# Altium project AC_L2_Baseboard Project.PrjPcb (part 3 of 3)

## Sheet AC_L2_Baseboard_HPGP_ZC.SchDoc
size 431 x 279 mm; DocumentNumber: 5; SheetNumber: 5; SheetTotal: 11; PageSetup: Record=PageOptions¦CenterHorizontal=True¦CenterVertical=True¦PrintScale=0.69¦XCorrection=1.00¦YCorrection=1.00¦PrintKind=0¦BorderSize=5000000¦LeftOffset=0¦BottomOffset=0¦Orientation=2¦PaperLength=1000¦PaperWidth=1000¦Scale=100¦PaperSource=15¦PrintQuality=600¦MediaType=1¦DitherType=10¦PaperKind=Letter¦PrintScaleMode=1
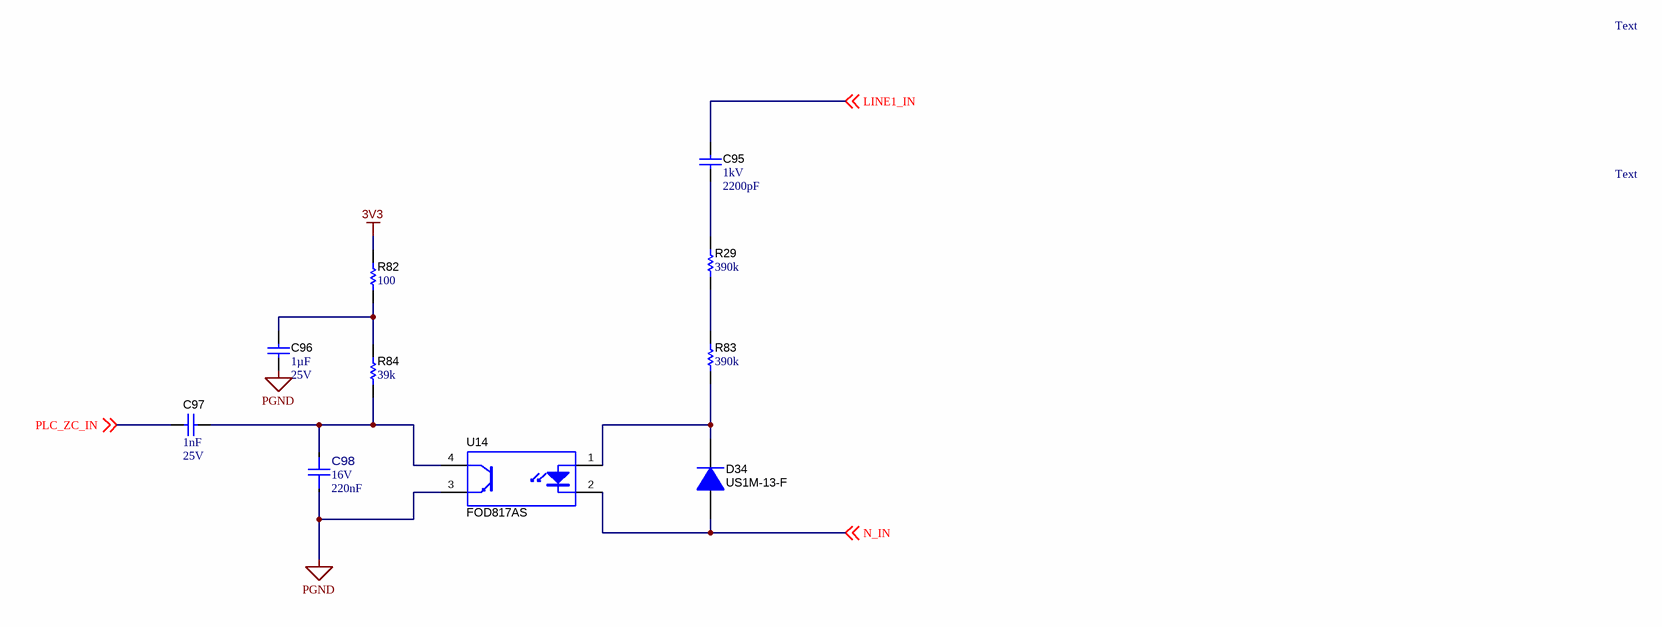
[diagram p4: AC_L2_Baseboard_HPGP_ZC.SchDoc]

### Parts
C95  VDC_V: 1kV  ValueDisplayed: 2200pF  [1206]  (hidden comment: GRM31BR73A222KW01L)
C96  Cap_F: 1µF  VDC_V: 25V  [0603]  (hidden comment: GCM188R71E105KA64D)
C97  Cap_F: 1nF  VDC_V: 25V  [0603]  (hidden comment: GRM188R71E102KA01D)
C98  VDC_V: 16V  Cap_F: 220nF  [FP-CC0603KRX7R7BB224_0603-MFG]  (hidden comment: CC0603KRX7R7BB224)
D34  US1M-13-F  [SMA]
R29  ValueDisplayed: 390k  [1206]  (hidden comment: CRCW1206390KJNEA)
R82  ValueDisplayed: 100  [0603]  (hidden comment: CRCW0603100RJNEA)
R83  ValueDisplayed: 390k  [1206]  (hidden comment: CRCW1206390KJNEA)
R84  ValueDisplayed: 39k  [0603]  (hidden comment: RC0603JR-0739KL)
U14  FOD817AS  [N04C]

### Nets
3V3: R82.2
PGND: C96.2 C98.1 U14.3(E)
LINE1_IN: C95.1 ; off-sheet LINE1_IN
N_IN: D34.2(A) U14.2(K) ; off-sheet N_IN
PLC_ZC_IN: C97.2 ; off-sheet PLC_ZC_IN
NetC95_2: C95.2 R29.2
NetC96_1: C96.1 R82.1 R84.2
NetC97_1: C97.1 C98.2 R84.1 U14.4(C)
NetD34_1: D34.1(K) R83.1 U14.1(A)
NetR29_1: R29.1 R83.2

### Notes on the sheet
- Text

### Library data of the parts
C95 = CMP-0008918-2: CAP, CERM, 2200 pF, 1000 V, +/- 10%, X7R, 1206; Manufacturer: MuRata; TaMin_C: -55°C; Polarized: N; SizeAreaWB_mm2: 10.92; Value1: Unknown; U/M: EA; Value: 2200pF; TaMax_C: 125°C; SizeZ_mm: 1.35; SizeX_mm: 3.2; SizeY_mm: 1.6; Value2: 1000V; SizeArea_mm2: 5.12; Cap_F: 2.2nF; AEC Category: Q200
C96 = CMP-0007139-2: CAP, CERM, 1 uF, 25 V, +/- 10%, X7R, AEC-Q200 Grade 1, 0603; Manufacturer: MuRata; TaMin_C: -55°C; Polarized: N; SizeAreaWB_mm2: 4.68; Value1: Unknown; U/M: EA; Value: 1uF; TaMax_C: 125°C; SizeZ_mm: 1; SizeX_mm: 1.6; SizeY_mm: 0.8; SizeArea_mm2: 1.28; AEC Qualified: Y; AEC Category: Q200
C97 = CMP-0007402-2: CAP, CERM, 1000 pF, 25 V, +/- 10%, X7R, 0603; Manufacturer: MuRata; TaMin_C: -55°C; Polarized: N; SizeAreaWB_mm2: 4.68; Value1: Unknown; U/M: EA; Value: 1000pF; TaMax_C: 125°C; SizeZ_mm: 1; SizeX_mm: 1.6; SizeY_mm: 0.8; SizeArea_mm2: 1.28; AEC Category: Q200
C98 = CMP-0091480-1: 0603 0.22 uF 16 V ±10 % Tolerance X7R SMT Multilayer Ceramic Capacitor; Manufacturer: Yageo; TempCo: 15%; AEC Qualified: No; Tolerance_%: 10%; Value: 220nF; SizeZ_mm: 0.9mm
D34 = CMP-0076882-1: Diode, Ultrafast, 1000 V, 1 A, SMA; Manufacturer: Diodes Inc.; SizeAreaWB_mm2: 37.3428; Vr_V: 1kV; SizeArea_mm2: 16.3228; TJmax_C: 150°C; AEC Category: Q101; Value: 1000V; SizeZ_mm: 2.87; Green_REACh: Incomplete; Io_A: 1A; Vf_V: 1.7V; SizeY_mm: 2.92; Green_Lifecycle: Not Set; U/M: EA; SizeX_mm: 5.59; RJC_CperW: 30.0
R29 R83 = CMP-0018664-3: RES, 390 k, 5%, 0.25 W, AEC-Q200 Grade 0, 1206; Manufacturer: Vishay-Dale; Power_W: 250mW; TempCo: 200 ppm/C; Value: 390k; EIA_Code: E24; SizeX_mm: 3.2; SizeY_mm: 1.6; SizeZ_mm: 1.35; Value2: 0.25W; SizeArea_mm2: 5.12; AEC Qualified: Y; VDC_V: 200V; AEC Category: Q200; AEC Grade: 0
R82 = CMP-0025700-2: RES, 100, 5%, 0.1 W, 0603; Manufacturer: Vishay-Dale; Power_W: 100mW; TempCo: 200 ppm/C; Value_Code: 100R; U/M: EA; Value: 100; EIA_Code: E24; SizeX_mm: 1.6; SizeY_mm: 0.8; SizeZ_mm: 1; Value2: 0.1W; SizeArea_mm2: 1.28; VDC_V: 75V; AEC Category: Q200
R84 = CMP-0025917-5: RES, 39 k, 5%, 0.1 W, 0603; Manufacturer: Yageo; Power_W: 100mW; TempCo: 100 ppm/C; Value_Code: 39k0; Value: 39k; EIA_Code: E24; SizeX_mm: 1.6; SizeY_mm: 0.8; SizeZ_mm: 1; Value2: 0.1W; SizeArea_mm2: 1.28; AEC Qualified: N; VDC_V: 75V; AEC Category: Q200; SizeAreaWB_mm2: 4.68
U14 = CMP-0006177-3: Optocoupler, 5 kV, 80-160% CTR, SMT; Manufacturer: Fairchild Semiconductor; CTR (Max): 160%; CTR (Min): 80%; Voltage_Isolation_Vrms: 5kV

## Sheet AC_L2_Baseboard_Pilot_Wire_ADC.SchDoc
size 431 x 279 mm; DocumentNumber: 6; SheetNumber: 6; SheetTotal: 11; PageSetup: Record=PageOptions¦CenterHorizontal=True¦CenterVertical=True¦PrintScale=0.69¦XCorrection=1.00¦YCorrection=1.00¦PrintKind=0¦BorderSize=5000000¦LeftOffset=0¦BottomOffset=0¦Orientation=2¦PaperLength=1000¦PaperWidth=1000¦Scale=100¦PaperSource=15¦PrintQuality=600¦MediaType=1¦DitherType=10¦PaperKind=Letter¦PrintScaleMode=1
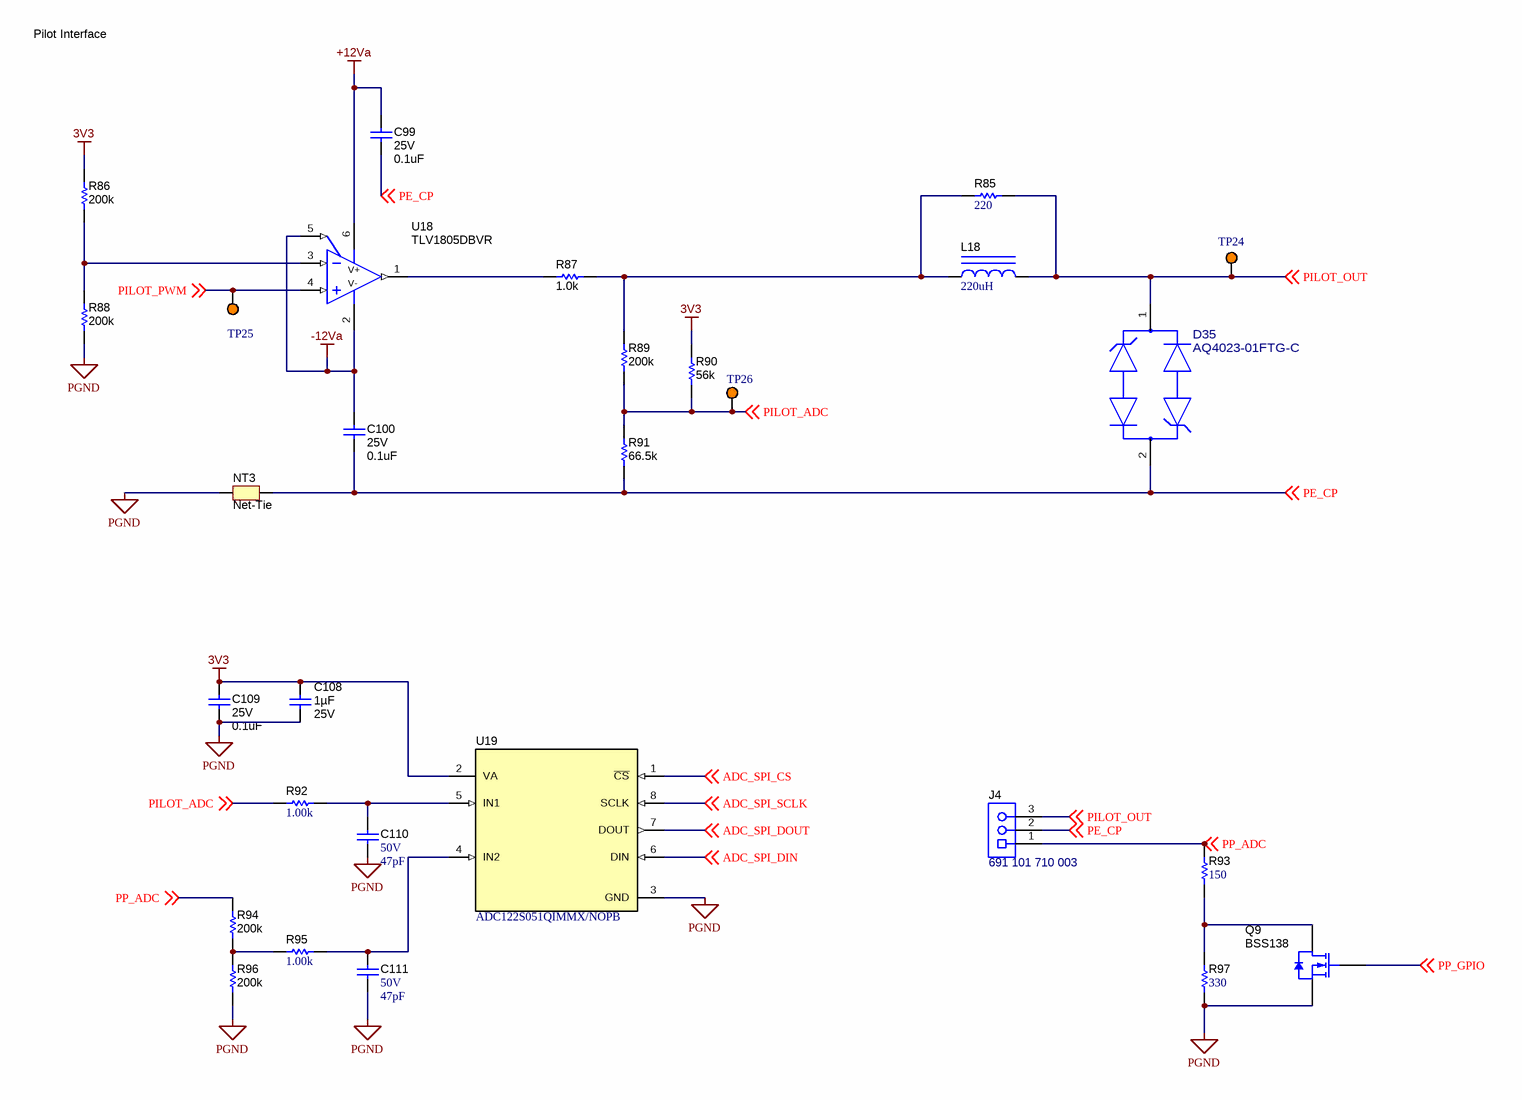
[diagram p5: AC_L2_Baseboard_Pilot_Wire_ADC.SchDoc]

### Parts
C99  VDC_V: 25V  ValueDisplayed: 0.1uF  [0603]  (hidden comment: GRM188R71E104KA01D)
C100  VDC_V: 25V  ValueDisplayed: 0.1uF  [0603]  (hidden comment: GRM188R71E104KA01D)
C108  Cap_F: 1µF  VDC_V: 25V  [0603]  (hidden comment: CGJ3E1X7R1E105K080AC)
C109  VDC_V: 25V  ValueDisplayed: 0.1uF  [0603]  (hidden comment: GRM188R71E104KA01D)
C110  VDC_V: 50V  ValueDisplayed: 47pF  [0603]  (hidden comment: CGA3E2NP01H470J080AA)
C111  VDC_V: 50V  ValueDisplayed: 47pF  [0603]  (hidden comment: CGA3E2NP01H470J080AA)
D35  AQ4023-01FTG-C  [FP-AQ4023-01FTG-C_SOD323-MFG]
J4  691 101 710 003  [Wurth_691101710003]
L18  ValueDisplayed: 220uH  [WE-PD_7345_PlasticBase]  (hidden comment: 7447779222)
NT3  Net-Tie  [Net-Tie_0805_HV_NoOverlay]  (net tie, no BOM)
Q9  BSS138  [SOT-23]
R85  ValueDisplayed: 220  [0603]  (hidden comment: CRCW0603220RJNEA)
R86  ValueDisplayed: 200k  [0603]  (hidden comment: RC0603FR-07200KL)
R87  ValueDisplayed: 1.0k  [0603]  (hidden comment: RC0603JR-071KL)
R88  ValueDisplayed: 200k  [0603]  (hidden comment: RC0603FR-07200KL)
R89  ValueDisplayed: 200k  [0603]  (hidden comment: RC0603FR-07200KL)
R90  ValueDisplayed: 56k  [0603]  (hidden comment: RC0603JR-0756KL)
R91  ValueDisplayed: 66.5k  [0603]  (hidden comment: RC0603FR-0766K5L)
R92  ValueDisplayed: 1.00k  [0603]  (hidden comment: RC0603FR-071KL)
R93  ValueDisplayed: 150  [0805_HV]  (hidden comment: CRCW0805150RFKEA)
R94  ValueDisplayed: 200k  [0603]  (hidden comment: RC0603FR-07200KL)
R95  ValueDisplayed: 1.00k  [0603]  (hidden comment: RC0603FR-071KL)
R96  ValueDisplayed: 200k  [0603]  (hidden comment: RC0603FR-07200KL)
R97  ValueDisplayed: 330  [0805_HV]  (hidden comment: CRCW0805330RFKEAC)
TP24  5003  [Keystone5003]  (value not drawn)
TP25  5003  [Keystone5003]  (value not drawn)
TP26  5003  [Keystone5003]  (value not drawn)
U18  TLV1805DBVR  [DBV0006A_N]
U19  ADC122S051QIMMX/NOPB  [DGK0008A_N]

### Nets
3V3: C108.1 C109.1 R86.2 R90.2 U19.2(VA)
+12Va: C99.1 U18.6(V+)
-12Va: C100.1 U18.2(V-) U18.5(SD)
PGND: C108.2 C109.2 C110.2 C111.2 NT3.1 Q9.2(S) R88.1 R96.1 R97.1 U19.3(GND)
ADC_SPI_CS: U19.1(~{CS}) ; off-sheet ADC_SPI_CS
ADC_SPI_DIN: U19.6(DIN) ; off-sheet ADC_SPI_DIN
ADC_SPI_DOUT: U19.7(DOUT) ; off-sheet ADC_SPI_DOUT
ADC_SPI_SCLK: U19.8(SCLK) ; off-sheet ADC_SPI_SCLK
PE_CP: C99.2 C100.2 D35.2 J4.2 NT3.2 R91.1 ; off-sheet PE_CP
PILOT_ADC: R89.1 R90.1 R91.2 R92.1 TP26.1 ; off-sheet PILOT_ADC
PILOT_OUT: D35.1 J4.3 L18.2 R85.2 TP24.1 ; off-sheet PILOT_OUT
PILOT_PWM: TP25.1 U18.4(IN+) ; off-sheet PILOT_PWM
PP_ADC: J4.1 R93.2 R94.2 ; off-sheet PP_ADC
PP_GPIO: Q9.1(G) ; off-sheet PP_GPIO
NetC110_1: C110.1 R92.2 U19.5(IN1)
NetC111_1: C111.1 R95.2 U19.4(IN2)
NetL18_1: L18.1 R85.1 R87.2 R89.2
NetQ9_3: Q9.3(D) R93.1 R97.2
NetR86_1: R86.1 R88.2 U18.3(IN-)
NetR87_1: R87.1 U18.1(OUT)
NetR94_1: R94.1 R95.1 R96.2

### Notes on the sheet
- Pilot Interface

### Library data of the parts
C99 C100 C109 = CMP-0007404-4: CAP, CERM, 0.1 uF, 25 V, +/- 10%, X7R, 0603; Manufacturer: MuRata; TaMin_C: -55°C; Polarized: N; SizeAreaWB_mm2: 4.68; Value1: Unknown; U/M: EA; Value: 0.1uF; TaMax_C: 125°C; SizeZ_mm: 1; SizeX_mm: 1.6; SizeY_mm: 0.8; SizeArea_mm2: 1.28; Cap_F: 100nF; AEC Category: Q200
C108 = CMP-0083856-1: CAP, CERM, 1 µF, 25 V,+/- 10%, X7R, 0603; Manufacturer: TDK; TaMin_C: -55°C; Polarized: N; SizeAreaWB_mm2: 4.68; U/M: EA; Value: 1uF; TaMax_C: 125°C; SizeZ_mm: 1; SizeX_mm: 1.6; SizeY_mm: 0.8; SizeArea_mm2: 1.28; AEC Category: Q200
C110 C111 = CMP-0080062-1: CAP, CERM, 47 pF, 50 V,+/- 5%, C0G/NP0, AEC-Q200 Grade 0, 0603; Manufacturer: TDK; TaMin_C: -55°C; Polarized: N; SizeAreaWB_mm2: 4.68; U/M: EA; Value: 47pF; TaMax_C: 150°C; SizeZ_mm: 1; SizeX_mm: 1.6; SizeY_mm: 0.8; SizeArea_mm2: 1.28; AEC Qualified: Y; AEC Grade: 0; AEC Category: Q200
D35 = CMP-0095193-1: ESD Suppressor Diode TVS Bi-Dir 15V Automotive 2-Pin SOD-323 T/R; Manufacturer: Littelfuse; AEC Grade: Grade 0; Standoff Height: 0mm; Breakdown Voltage: 16V; Direction: Bidirectional; AEC Qualified: Yes; Number Of Channels: 1; ValueDisplayed: 1.3pF; SizeZ_mm: 1mm; Ipp: 12A; Ppk: 450W; Clamping Voltage: 37.5V
J4 = CMP-0054829-1: Terminal Block, 5 mm, 3x1, Tin, TH; Manufacturer: Wurth Elektronik; CNHeader: FALSE; Green_Lifecycle: Active; Green_REACh: Passed; CT: TRUE
L18 = CMP-0064815-2: Inductor, Shielded Drum Core, Metal Composite, 220 uH, 0.44 A, 0.92 ohm, SMD; Manufacturer: Wurth Elektronik; Isat: 0.54A @ 10% inductance drop; Irms: 0.44A @ 40C rise; Green_Lifecycle: Active; SizeAreaWB_mm2: 86.49; DCR_ohm: 0.92; Green_REACh: Passed; Value: 220uH; Imax_A: 440mA; SizeZ_mm: 4.5; SizeX_mm: 7.3; Value2: 0.44A; SizeArea_mm2: 53.29; Ind_H: 220µH; AEC Category: Q200
NT3 = CMP-0078142-2: Single point connection between nets.
Q9 = CMP-0000755-1: MOSFET, N-CH, 50 V, 0.22 A, SOT-23; Alternate Manufacturer: None; Manufacturer: Fairchild Semiconductor; SizeZ_mm: 1.1; ChType: N; Value2: 1.7 nC; VdsMax_V: 50V; SizeX_mm: 2.5; SizeY_mm: 3; Vgs_V: 20V; Value: 50V; Rdson45_ohm: 6; SizeArea_mm2: 7.5; AEC Category: Q101; IdsMax_A: 220mA; SizeAreaWB_mm2: 14; U/M: EA; QgTyp_nC: 1.7
R85 = CMP-0025756-4: RES, 220, 5%, 0.1 W, AEC-Q200 Grade 0, 0603; Manufacturer: Vishay-Dale; Power_W: 100mW; TempCo: 200 ppm/C; Value_Code: 220R; Value: 220; EIA_Code: E24; SizeX_mm: 1.6; SizeY_mm: 0.8; SizeZ_mm: 1; Value2: 0.1W; SizeArea_mm2: 1.28; AEC Qualified: Y; VDC_V: 75V; AEC Category: Q200; AEC Grade: 0
R86 R88 R89 R94 R96 = CMP-0022901-4: RES, 200 k, 1%, 0.1 W, 0603; Manufacturer: Yageo; Power_W: 100mW; TempCo: 100 ppm/C; Value: 200k; EIA_Code: E96; SizeX_mm: 1.6; SizeY_mm: 0.8; SizeZ_mm: 1; Value2: 0.1W; AEC Qualified: N; VDC_V: 75V; AEC Category: Q200; SizeArea_mm2: 1.28; SizeAreaWB_mm2: 4.68
R87 = CMP-0025899-5: RES, 1.0 k, 5%, 0.1 W, 0603; Manufacturer: Yageo; Power_W: 100mW; TempCo: 100 ppm/C; Value_Code: 1k00; Value: 1.0k; EIA_Code: E24; Res_ohm: 1k; SizeX_mm: 1.6; SizeY_mm: 0.8; SizeZ_mm: 1; Value2: 0.1W; SizeArea_mm2: 1.28; AEC Qualified: N; VDC_V: 75V; AEC Category: Q200; SizeAreaWB_mm2: 4.68
R90 = CMP-0025931-5: RES, 56 k, 5%, 0.1 W, 0603; Manufacturer: Yageo; Power_W: 100mW; TempCo: 100 ppm/C; Value_Code: 56k0; Value: 56k; EIA_Code: E24; SizeX_mm: 1.6; SizeY_mm: 0.8; SizeZ_mm: 1; Value2: 0.1W; SizeArea_mm2: 1.28; AEC Qualified: N; VDC_V: 75V; AEC Category: Q200; SizeAreaWB_mm2: 4.68
R91 = CMP-0023232-5: RES, 66.5 k, 1%, 0.1 W, 0603; Manufacturer: Yageo; Power_W: 100mW; TempCo: 100 ppm/C; Value_Code: 66k5; Value: 66.5k; EIA_Code: E96; SizeZ_mm: 1; Value2: 0.1W; SizeArea_mm2: 1.28; AEC Qualified: N; VDC_V: 75V; AEC Category: Q200; SizeAreaWB_mm2: 4.68; SizeX_mm: 1.6; SizeY_mm: 0.8
R92 R95 = CMP-0022895-5: RES, 1.00 k, 1%, 0.1 W, 0603; Manufacturer: Yageo; Power_W: 100mW; TempCo: 100 ppm/C; Value_Code: 1k00; Value: 1.00k; EIA_Code: E96; Res_ohm: 1k; SizeX_mm: 1.6; SizeY_mm: 0.8; SizeZ_mm: 1; Value2: 0.1W; SizeArea_mm2: 1.28; AEC Qualified: N; VDC_V: 75V; AEC Category: Q200; SizeAreaWB_mm2: 4.68
R93 = CMP-0020904-3: RES, 150, 1%, 0.125 W, AEC-Q200 Grade 0, 0805; Manufacturer: Vishay-Dale; Power_W: 125mW; TempCo: 100 ppm/C; Value_Code: 150R; Value: 150; EIA_Code: E96; SizeX_mm: 2; SizeY_mm: 1.25; SizeZ_mm: 1.45; Value2: 0.125W; SizeArea_mm2: 2.5; AEC Qualified: Y; VDC_V: 150V; AEC Category: Q200; AEC Grade: 0
R97 = CMP-0082535-1: RES, 330, 1%, 0.125 W, 0805; Manufacturer: Vishay-Dale; Power_W: 125mW; TempCo: 100 ppm/C; SizeAreaWB_mm2: 6.75; Value_Code: 330R; Value: 330; SizeX_mm: 2; SizeY_mm: 1.25; SizeZ_mm: 1.45; Value2: 0.125W; SizeArea_mm2: 2.5; AEC Qualified: N; VDC_V: 150V; AEC Category: Q200
TP24-TP26 = CMP-0055140-1: Test Point, Miniature, Orange, TH; Manufacturer: Keystone; CNHeader: FALSE; Green_Lifecycle: Active; Green_REACh: Passed; ContactFinish: Silver; CT: TRUE
U18 = CMP-0080757-2: 40 V, microPower, Push-Pull Comparator with Shutdown, DBV0006A (SOT-23-6); Alternate Manufacturer: Texas Instruments; SizeAreaWB_mm2: 14.82; SizeZ_mm: 1.45; SizeX_mm: 2.8; SizeY_mm: 2.9; SizeArea_mm2: 8.12; CompType: IC; AEC Qualified: N; AEC Category: Q200
U19 = CMP-0077684-1: 2 Channel, 200 ksps to 500 ksps  12-Bit A/D Converter, DGK0008A (VSSOP-8); Alternate PartNumber: ADC122S051QIMM/NOPB; Alternate Manufacturer: Texas Instruments; SizeAreaWB_mm2: 35.955; SizeZ_mm: 1.1; SizeX_mm: 5.05; SizeY_mm: 3.1; SizeArea_mm2: 15.655; CompType: IC; AEC Qualified: Y; AEC Category: Q200

## Sheet AC_L2_Baseboard_PlugLock.SchDoc
size 431 x 279 mm; DocumentNumber: 7; SheetNumber: 7; SheetTotal: 11; PageSetup: Record=PageOptions¦CenterHorizontal=True¦CenterVertical=True¦PrintScale=0.69¦XCorrection=1.00¦YCorrection=1.00¦PrintKind=0¦BorderSize=5000000¦LeftOffset=0¦BottomOffset=0¦Orientation=2¦PaperLength=1000¦PaperWidth=1000¦Scale=100¦PaperSource=15¦PrintQuality=600¦MediaType=1¦DitherType=10¦PaperKind=Letter¦PrintScaleMode=1
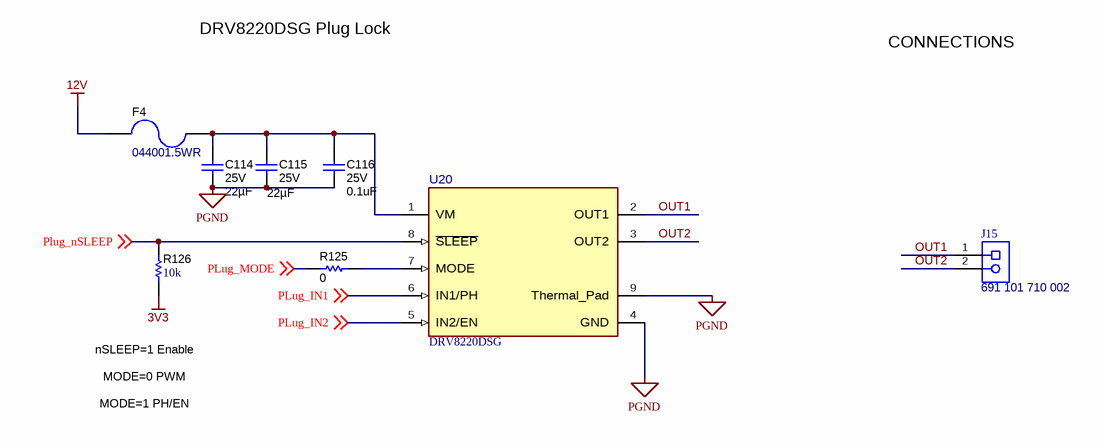
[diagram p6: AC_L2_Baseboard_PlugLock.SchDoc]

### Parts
C114  VDC_V: 25V  ValueDisplayed: 22µF  [1210_270]  (hidden comment: CC1210KKX7R8BB226)
C115  VDC_V: 25V  ValueDisplayed: 22µF  [1210_270]  (hidden comment: CC1210KKX7R8BB226)
C116  VDC_V: 25V  ValueDisplayed: 0.1uF  [0402S]  (hidden comment: TMK105B7104MV-FR)
F4  044001.5WR  [1206]
J15  691 101 710 002  [Wurth_691101710002]
R125  ValueDisplayed: 0  [0603]  (hidden comment: RCS06030000Z0EA)
R126  ValueDisplayed: 10k  [0603]  (hidden comment: RC0603JR-0710KL)
U20  DRV8220DSG  [DSG0008A-MFG]

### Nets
3V3: R126.1
12V: F4.2  [project net 12V_In]
PGND: C114.2 C115.2 C116.2 U20.4(GND) U20.9(Thermal_Pad)
OUT1: J15.1 U20.2(OUT1)
OUT2: J15.2 U20.3(OUT2)
PLug_IN1: U20.6(IN1/PH) ; off-sheet PLug_IN1
PLug_IN2: U20.5(IN2/EN) ; off-sheet PLug_IN2
PLug_MODE: R125.2 ; off-sheet PLug_MODE
Plug_nSLEEP: R126.2 U20.8(~{SLEEP}) ; off-sheet Plug_nSLEEP
NetC114_1: C114.1 C115.1 C116.1 F4.1 U20.1(VM)
NetR125_1: R125.1 U20.7(MODE)

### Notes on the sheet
- DRV8220DSG Plug Lock
- CONNECTIONS
- MODE=0 PWM
- nSLEEP=1 Enable
- MODE=1 PH/EN

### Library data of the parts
C114 C115 = CMP-0082267-1: CAP, CERM, 22 µF, 25 V,+/- 10%, X7R, 1210; Manufacturer: Yageo; TaMin_C: -55°C; ESR_ohm: 1m; Polarized: N; SizeAreaWB_mm2: 14.7; Value1: 0.001 ohm; U/M: EA; Value: 22uF; TaMax_C: 125°C; SizeZ_mm: 2.7; SizeX_mm: 3.2; SizeY_mm: 2.5; Cap_Case: 1210; SizeArea_mm2: 8; AEC Category: Q200
C116 = CMP-0006720-2: CAP, CERM, 0.1 uF, 25 V, +/- 20%, X7R, 0402; Manufacturer: Taiyo Yuden; TaMin_C: -55°C; Polarized: N; SizeAreaWB_mm2: 3; Value1: Unknown; U/M: EA; Value: 0.1uF; TaMax_C: 125°C; SizeZ_mm: 0.6; SizeX_mm: 1; SizeY_mm: 0.5; Cap_Case: 0402; Cap_F: 100nF; AEC Category: Q200
F4 = CMP-0003461-2: Fuse, 1.5 A, 50VAC/VDC, SMD; Manufacturer: Littelfuse; Irating_A: 1.5A; SizeAreaWB_mm2: 10.92; Interrupt_AC: 50A; VAC_V: 50V; SizeZ_mm: 1.35; SizeX_mm: 3.2; SizeY_mm: 1.6; SizeArea_mm2: 5.12; Rtyp_Ohm: 0.1759; MeltingTyp: 0.50652
J15 = CMP-0054828-1: Terminal Block, 5 mm, 2x1, Tin, TH; Manufacturer: Wurth Elektronik; CNHeader: FALSE; Green_Lifecycle: Active; Green_REACh: Passed; CT: TRUE
R125 = CMP-0081973-1: RES, 0, 0%, 0.25 W, AEC-Q200 Grade 0, 0603; Manufacturer: Vishay-Dale; SizeAreaWB_mm2: 4.68; SizeArea_mm2: 1.28; AEC Qualified: Y; AEC Category: Q200; Value: 0; SizeZ_mm: 1; SizeY_mm: 0.8; Power_W: 250mW; Value2: 0.25W; SizeX_mm: 1.6
R126 = CMP-0025886-5: RES, 10 k, 5%, 0.1 W, 0603; Manufacturer: Yageo; Power_W: 100mW; TempCo: 100 ppm/C; Value_Code: 10k0; Value: 10k; EIA_Code: E24; SizeX_mm: 1.6; SizeY_mm: 0.8; SizeZ_mm: 1; Value2: 0.1W; SizeArea_mm2: 1.28; AEC Qualified: N; VDC_V: 75V; AEC Category: Q200; SizeAreaWB_mm2: 4.68
U20 = CMP-0090279-1: 1.6A H-bridge motor driver, PWM, PH/EN, ½ bridge control, with low power sleep mode; Manufacturer: Texas Instruments; Number Of Outputs: 2; Standoff Height: 0mm; TaMin_C: -40°C; Max Supply Voltage: 18V; TJmax_C: +150°C; Motor Type: Brushed; Min Supply Voltage: 4.5V; TaMax_C: +125°C; Switching Frequency: 100kHz; AEC Qualified: No; SizeZ_mm: 0.8mm

## Sheet AC_L2_Baseboard_RCD.SchDoc
size 431 x 279 mm; Date: Not shown in title block; ApprovedBy: Not shown in title block; CheckedBy: Not shown in title block; Author: Not shown in title block; CompanyName: Not shown in title block; Engineer: Not shown in title block; Organization: Not shown in title block; Address1: Not shown in title block; Address2: Not shown in title block; Address3: Not shown in title block; Address4: Not shown in title block; DocumentNumber: 8; Revision: Use project parameter SCH_Rev; SheetNumber: 8; SheetTotal: 11; PageSetup: Record=PageOptions¦CenterHorizontal=True¦CenterVertical=True¦PrintScale=1.00¦XCorrection=1.00¦YCorrection=1.00¦PrintKind=0¦BorderSize=5000000¦LeftOffset=0¦BottomOffset=0¦Orientation=2¦PaperLength=1000¦PaperWidth=1000¦Scale=100¦PaperSource=15¦PrintQuality=600¦MediaType=1¦DitherType=10¦PaperKind=Letter¦PrintScaleMode=1
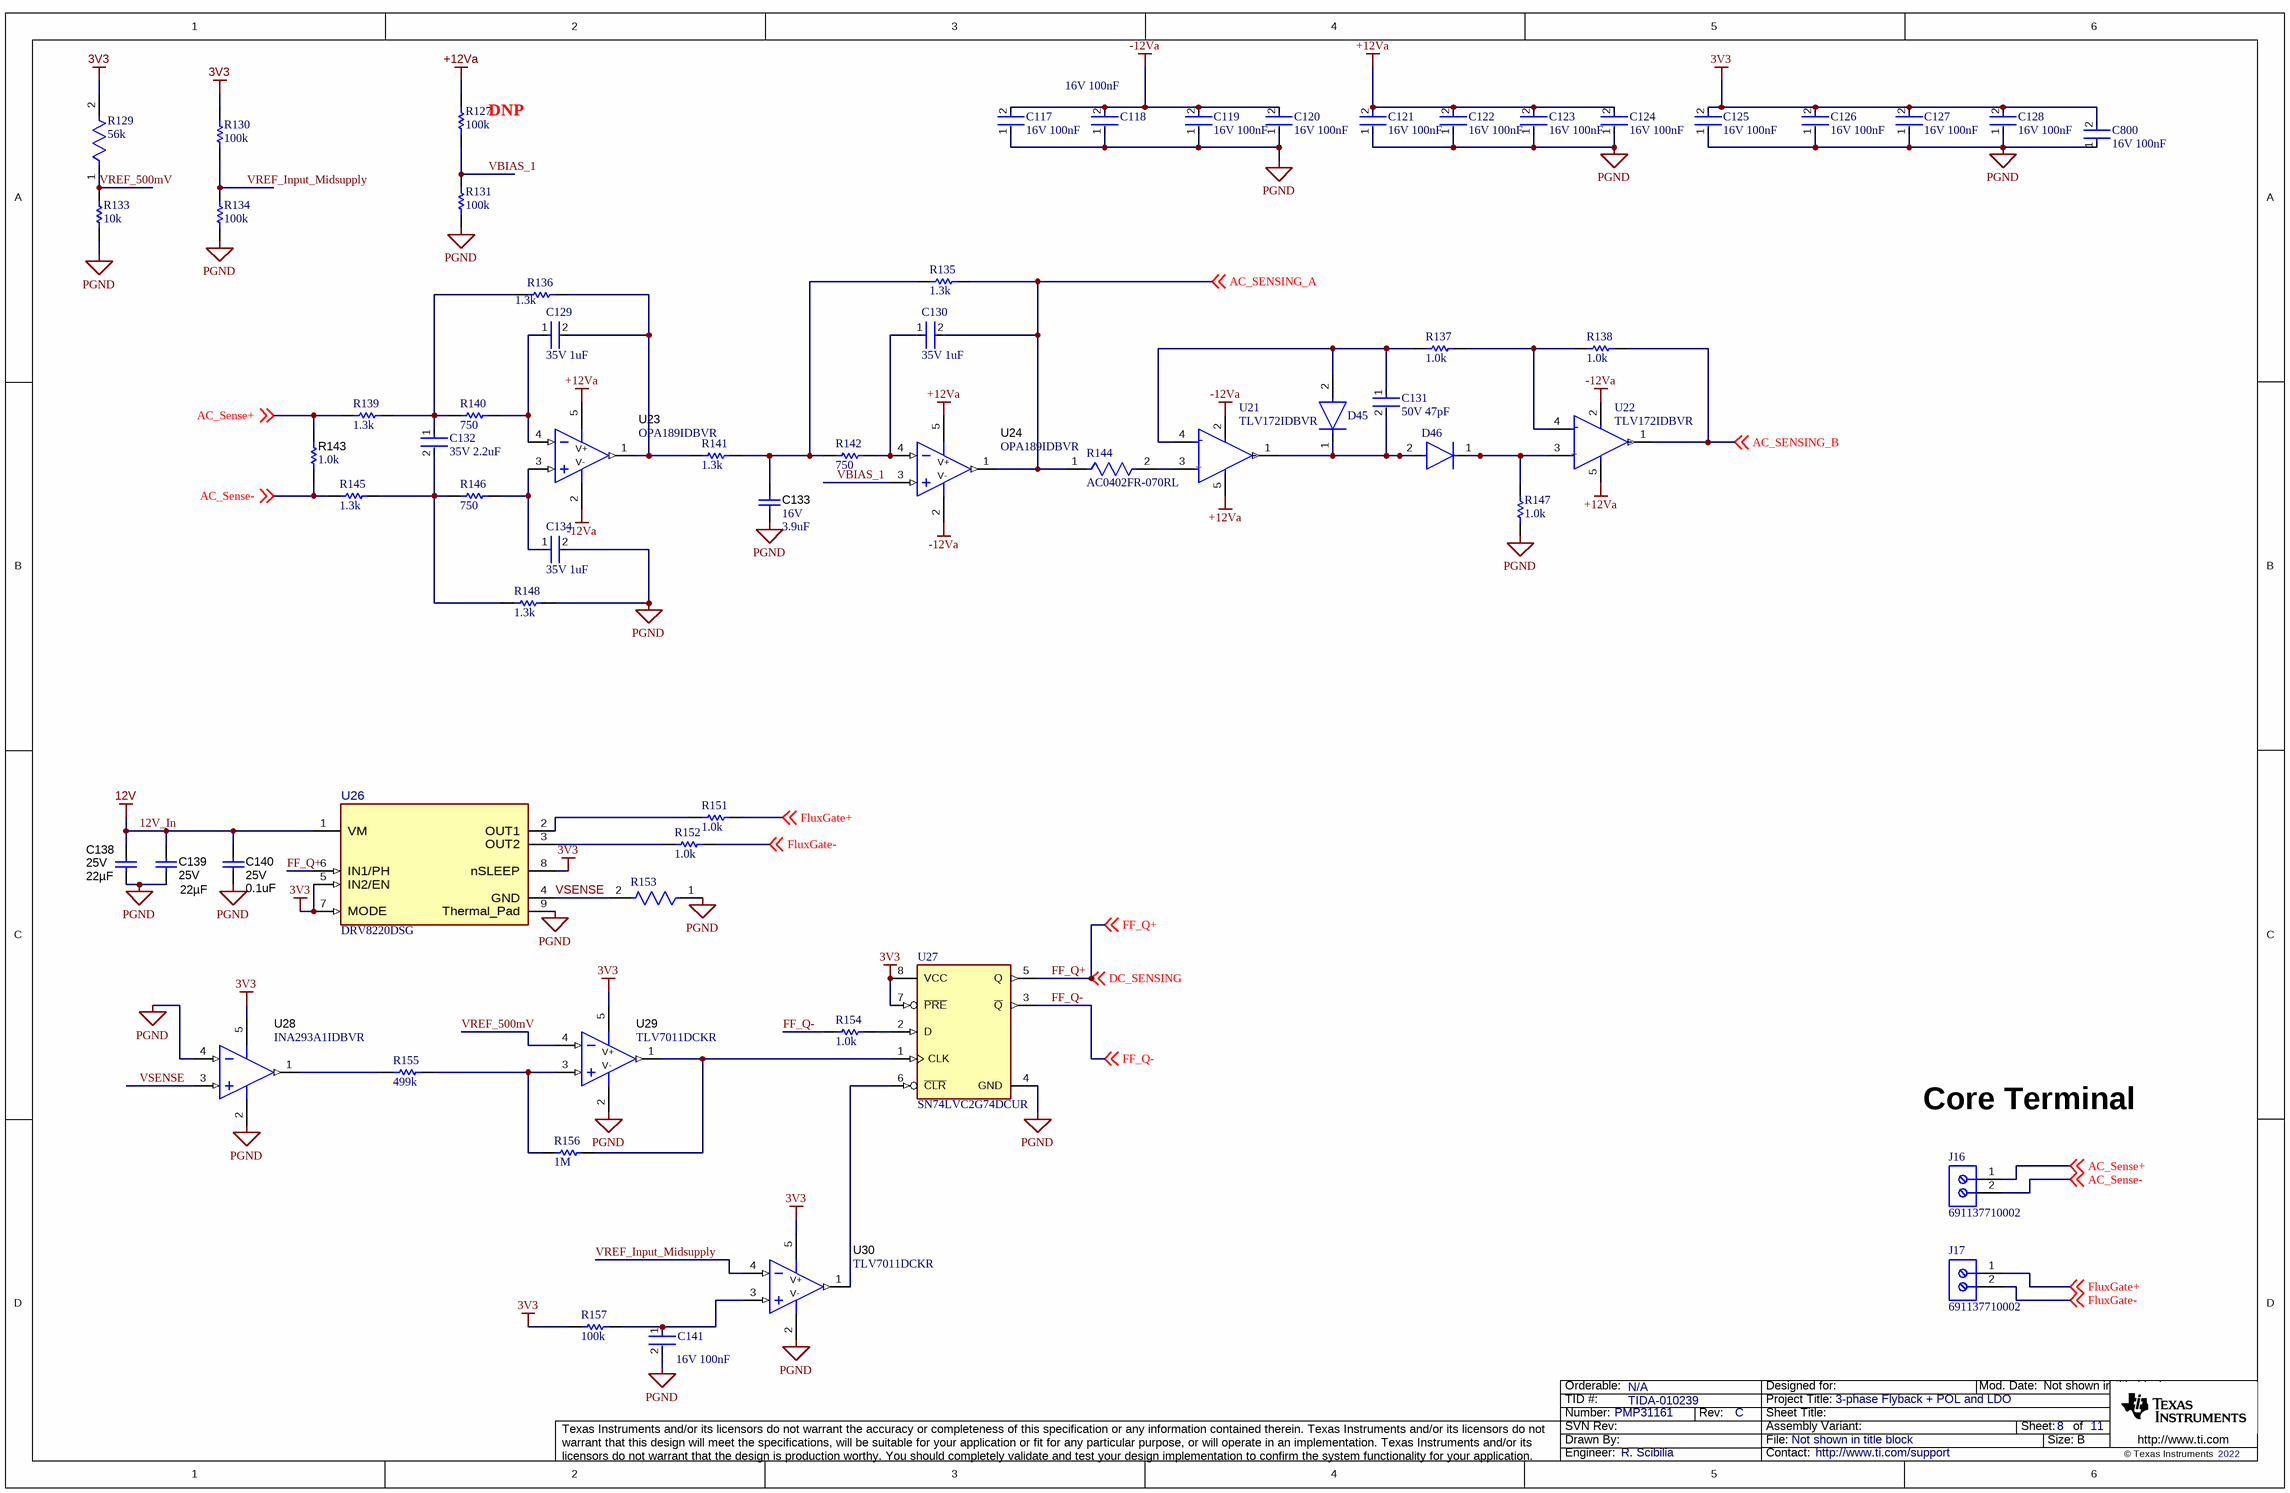
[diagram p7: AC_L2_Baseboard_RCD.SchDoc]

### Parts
C117  16V 100nF  [FP-GRT033-0_03-IPC_B]
C118  16V 100nF  [FP-GRT033-0_03-IPC_B]
C119  16V 100nF  [FP-GRT033-0_03-IPC_B]
C120  16V 100nF  [FP-GRT033-0_03-IPC_B]
C121  16V 100nF  [FP-GRT033-0_03-IPC_B]
C122  16V 100nF  [FP-GRT033-0_03-IPC_B]
C123  16V 100nF  [FP-GRT033-0_03-IPC_B]
C124  16V 100nF  [FP-GRT033-0_03-IPC_B]
C125  16V 100nF  [FP-GRT033-0_03-IPC_B]
C126  16V 100nF  [FP-GRT033-0_03-IPC_B]
C127  16V 100nF  [FP-GRT033-0_03-IPC_B]
C128  16V 100nF  [FP-GRT033-0_03-IPC_B]
C129  35V 1uF  [FP-GRM155-0_1-MFG]
C130  35V 1uF  [FP-GRM155-0_1-MFG]
C131  50V 47pF  [FP-C0603-030-0_03-MFG]
C132  35V 2.2uF  [FP-GRM155-0_2-MFG]
C133  VDC_V: 16V  ValueDisplayed: 3.9uF  [1206L]  (hidden comment: C1206C395K4PACTU)
C134  35V 1uF  [FP-GRM155-0_1-MFG]
C138  VDC_V: 25V  ValueDisplayed: 22µF  [1210_270]  (hidden comment: CC1210KKX7R8BB226)
C139  VDC_V: 25V  ValueDisplayed: 22µF  [1210_270]  (hidden comment: CC1210KKX7R8BB226)
C140  VDC_V: 25V  ValueDisplayed: 0.1uF  [0402S]  (hidden comment: TMK105B7104MV-FR)
C141  16V 100nF  [FP-C0201-AB-MFG]
C800  16V 100nF  [FP-GRT033-0_03-IPC_B]
D45  1N914BWT  [FP-502-01-MFG]  (value not drawn)
D46  1N914BWT  [FP-502-01-MFG]  (value not drawn)
J16  691137710002  [691137710002]
J17  691137710002  [691137710002]
R127  100k  [RESC0603X28X15LL05T05]
R129  56k  [FP-RG1005-IPC_B]
R130  100k  [RESC0603X28X15LL05T05]
R131  100k  [RESC0603X28X15LL05T05]
R133  10k  [RESC0603X28X15LL05T05]
R134  100k  [RESC0603X28X15LL05T05]
R135  1.3k  [RESC0603X28X15LL05T05]
R136  1.3k  [RESC0603X28X15LL05T05]
R137  1.0k  [RESC0603X28X15NL05T05]
R138  1.0k  [RESC0603X28X15NL05T05]
R139  1.3k  [RESC0603X28X15LL05T05]
R140  750  [RESC0603X28X15LL05T05]
R141  1.3k  [RESC0603X28X15LL05T05]
R142  750  [RESC0603X28X15LL05T05]
R143  ValueDisplayed: 1.0k  [2512]  (hidden comment: ERJ-1TYJ102U)
R144  AC0402FR-070RL  [FP-AC0402-0_37-IPC_B]
R145  1.3k  [RESC0603X28X15LL05T05]
R146  750  [RESC0603X28X15LL05T05]
R147  1.0k  [RESC0603X28X15NL05T05]
R148  1.3k  [RESC0603X28X15LL05T05]
R151  1.0k  [RESC0603X28X15NL05T05]
R152  1.0k  [RESC0603X28X15NL05T05]
R153  CRCW12063R00JNEA  [FP-CRCW1206-e3-IPC_A]  (value not drawn)
R154  1.0k  [RESC0603X28X15NL05T05]
R155  499k  [RESC0603X28X15NL05T05]
R156  1M  [RESC0603X28X15LL05T05]
R157  100k  [RESC0603X28X15LL05T05]
U21  TLV172IDBVR  [FP-DBV0005A-IPC_C]
U22  TLV172IDBVR  [FP-DBV0005A-IPC_C]
U23  OPA189IDBVR  [DBV0005A_N]
U24  OPA189IDBVR  [DBV0005A_N]
U26  DRV8220DSG  [DSG0008A-MFG]
U27  SN74LVC2G74DCUR  [FP-DCU0008A-IPC_C]
U28  INA293A1IDBVR  [DBV0005A_M]
U29  TLV7011DCKR  [DCK0005A_N]
U30  TLV7011DCKR  [DCK0005A_N]

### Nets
3V3: C125.2 C126.2 C127.2 C128.2 C800.2 R129.2 R130.2 R157.1 U26.5(IN2/EN) U26.7(MODE) U26.8(nSLEEP) U27.7(~{PRE}) U27.8(VCC) U28.5(V+) U29.5(V+) U30.5(V+)
12V_In: C138.1 C139.1 C140.1 U26.1(VM)  [also labelled 12V]
+12Va: C121.2 C122.2 C123.2 C124.2 R127.2 U21.5(V+) U22.5(V+) U23.5(V+) U24.5(V+)
-12Va: C117.2 C118.2 C119.2 C120.2 U21.2(V-) U22.2(V-) U23.2(V-) U24.2(V-)
PGND: C117.1 C118.1 C119.1 C120.1 C121.1 C122.1 C123.1 C124.1 C125.1 C126.1 C127.1 C128.1 C133.2 C134.2 C138.2 C139.2 C140.2 C141.2 C800.1 R131.1 R133.1 R134.1 R147.1 R148.2 R153.1 U26.9(Thermal_Pad) U27.4(GND) U28.2(GND) U28.4(VIN-) U29.2(V-) U30.2(V-)
AC_Sense+: J16.1 R139.1 R143.2 ; off-sheet AC_Sense+
AC_Sense-: J16.2 R143.1 R145.1 ; off-sheet AC_Sense-
AC_SENSING_A: C130.2 R135.2 R144.1 U24.1(OUT) ; off-sheet AC_SENSING_A
AC_SENSING_B: R138.2 U22.1(OUT) ; off-sheet AC_SENSING_B
FF_Q+: U26.6(IN1/PH) U27.5(Q) ; off-sheet DC_SENSING, off-sheet FF_Q+  [also labelled DC_SENSING]
FF_Q-: R154.1 U27.3(~{Q}) ; off-sheet FF_Q-
FluxGate+: J17.1 R151.2 ; off-sheet FluxGate+
FluxGate-: J17.2 R152.2 ; off-sheet FluxGate-
VBIAS_1: R127.1 R131.2 U24.3(IN+)
VREF_500mV: R129.1 R133.2 U29.4(IN-)
VREF_Input_Midsupply: R130.1 R134.2 U30.4(IN-)
VSENSE: R153.2 U26.4(GND) U28.3(VIN+)
NetC129_1: C129.1 R140.2 U23.4(IN-)
NetC129_2: C129.2 R136.2 R141.1 U23.1(OUT)
NetC130_1: C130.1 R142.2 U24.4(IN-)
NetC131_1: C131.1 D45.2(A) R137.1 U21.4(-IN)
NetC131_2: C131.2 D45.1(C) D46.2(A) U21.1(OUT)
NetC132_1: C132.1 R136.1 R139.2 R140.1
NetC132_2: C132.2 R145.2 R146.1 R148.1
NetC133_1: C133.1 R135.1 R141.2 R142.1
NetC134_1: C134.1 R146.2 U23.3(IN+)
NetC141_1: C141.1 R157.2 U30.3(IN+)
NetD46_1: D46.1(C) R147.2 U22.3(+IN)
NetR137_2: R137.2 R138.1 U22.4(-IN)
NetR144_2: R144.2 U21.3(+IN)
NetR151_1: R151.1 U26.2(OUT1)
NetR152_1: R152.1 U26.3(OUT2)
NetR154_2: R154.2 U27.2(D)
NetR155_1: R155.1 U28.1(OUT)
NetR155_2: R155.2 R156.1 U29.3(IN+)
NetR156_2: R156.2 U27.1(CLK) U29.1(OUT)
NetU27_6: U27.6(~{CLR}) U30.1(OUT)

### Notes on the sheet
- (near R127) DNP
- Core Terminal

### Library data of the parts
C117-C128 C800 = CMP-06035-045930-1: Multi-Layer Ceramic Capacitor 100nF 16V X5R ±10% 0201 Paper T/R GRT033R61C104KE01D
C129 C130 C134 = CMP-06035-015284-1: Chip Multilayer Ceramic Capacitors for General Purpose, 0402, 1.0uF, X5R, 15%, 20%, 35V GRM155R6YA105ME11D
C131 = CMP-08246-004934-1: Multilayer Ceramic Capacitors 47pF ±10% 50V C0G SMD 0201 C0603C0G1H470K030BA
C132 = CMP-06035-031599-1: Chip Multilayer Ceramic Capacitors for General Purpose, 0402, 2.2uF, X5R, 15%, 10%, 35V GRM155R6YA225KE11D
C133 = CMP-0008620-2: CAP, CERM, 3.9 uF, 16 V, +/- 10%, X5R, 1206; Manufacturer: Kemet; TaMin_C: -55°C; ESR_ohm: 0.012; Polarized: N; SizeAreaWB_mm2: 10.92; Value1: 0.012 ohm; U/M: EA; Value: 3.9uF; TaMax_C: 85°C; SizeZ_mm: 1.35; SizeX_mm: 3.2; SizeY_mm: 1.6; Cap_Case: 1206; SizeArea_mm2: 5.12; Cap_F: 3.9µF; IRMS_A: 5.05A; AEC Category: Q200
C138 C139 = CMP-0082267-1: as C114 on sheet AC_L2_Baseboard_PlugLock
C140 = CMP-0006720-2: as C116 on sheet AC_L2_Baseboard_PlugLock
C141 = CMP-1033-00642-2: CAP CER 10000PF 16V 10% X5R 0201 C0201C103K4PACTU; Manufacturer: KEMET; Tolerance: 0.1; Material: Ceramic; Value: 10,000 pF; Standoff Height: 0mm; Temperature Coefficient: 30ppm/°C
D45 D46 = CMP-07163-000008-1: DIODE GEN PURP 75V 200MA SOD523F; Manufacturer: ON Semiconductor; Forward Current: 300mA; Capacitance: 4pF; Max Junction Temp: +150°C; Reverse Voltage: 100V; Value: 4pF; Peak Reverse Current: 5uA
J16 J17 = CMP-1502-03324-1: Series 1377 - 5.00 mm Horizontal Entry with Pressure Clamp WR-TBL, 2 pin; Manufacturer: Wurth Elektronik; Pin Number: 2; Pitch: 5.00mm
R127 R130 R131 R134 R157 = CMP-2004-00003-1: CRCW0201100KFNED; Manufacturer: Vishay
R129 = CMP-2002-01478-2: Automotive Metal Thin Film Chip Resistor, 0402, 56kΩ, 0.1%, 25ppm/°C, 0.0625W, 75V; Voltage Rating: 25V; Power Rating: 30mW; Resistance: 56kR; Max Power Dissipation: 63mW
R133 = CMP-2004-00015-1: CRCW020110K0FKED; Manufacturer: Vishay Dale
R135 R139 R141 R145 R148 = CMP-2004-03995-1: Part Number: CPF0201D3K83E1; Manufacturer: TE Connectivity / AMP
R136 = CMP-2004-00232-1: CRCW02011K30FNED; Manufacturer: Vishay Dale
R137 R138 R147 R151 R152 R154 = CMP-2004-00208-1: CRCW02011K00FKED; Manufacturer: Vishay Dale
R140 R142 R146 = CMP-2004-00846-1: CRCW0201750RFKED; Manufacturer: Vishay Dale
R143 = CMP-0016024-1: RES, 1.0 k, 5%, 1 W, 2512; Manufacturer: Panasonic; Power_W: 1W; TempCo: 200 ppm/C; Value_Code: 1k00; U/M: EA; Value: 1.0k; EIA_Code: E24; Res_ohm: 1k; SizeX_mm: 6.3; SizeY_mm: 3.2; SizeZ_mm: 0.71; SizeArea_mm2: 20.16; VDC_V: 200V; AEC Category: Q200
R144 = CMP-2002-01772-2: RESISTOR 0402 JUMPER ZERO OHM; Voltage Rating: 50V; Temperature Coefficient: 200ppm/°C; Tolerance: 1%; Power Rating: 62.5mW; Resistance: 0R
R153 = CMP-1014-00013-3: RES Thick Film, 3Ω, 5%, 0.25W, 200ppm/°C, 1206; Voltage Rating (DC): 200V; Resistance: 3R; Power Rating: 250mW
R155 = CMP-2004-00650-1: CRCW0201499KFNED; Manufacturer: Vishay Dale
R156 = CMP-2004-00269-1: CRCW02011M00FKED; Manufacturer: Vishay Dale
U21 U22 = CMP-04895-000139-1: IC OPAMP GP 1 CIRCUIT SOT23-5; Input Bias Current: 10pA; Slew Rate: 10V/µs; Gain Bandwidth Product: 10MHz; Input Offset Voltage (Vos): 500uV; Output Current per Channel: 75mA; Operating Supply Current: 1.6mA; Number of Channels: 1
U23 U24 = CMP-0860961-1: 14MHz, MUX-friendly, low-noise, zero-drift, RRO, CMOS precision operational amplifier, DBV0005A (SOT-23-5); Alternate Manufacturer: Texas Instruments; Alternate PartNumber: OPA189IDBVT; SizeY_mm: 2.9; AEC Qualified: N; SizeX_mm: 2.8; SizeAreaWB_mm2: 14.82; CompType: IC; SizeZ_mm: 1.45; Rating: Catalog; AEC Category: Q200; SizeArea_mm2: 8.12
U26 = CMP-0089585-1: Low-Voltage H-Bridge Driver; Manufacturer: Texas Instruments; TaMin_C: -40°C; Nominal Supply Current: 600-3000uA; Max Supply Voltage: 18V; TJmax_C: +150°C; Number Of Outputs: 2; Switching Frequency: 100kHz; Min Supply Voltage: 4.5V; AEC Qualified: No; SizeZ_mm: 0.8mm; Motor Type: Brushed; Standoff Height: 0mm; TaMax_C: +85°C
U27 = CMP-0859-00648-4: IC FF D-TYPE SNGL 1BIT US8; Manufacturer: Texas Instruments; Frequency: 140MHz; Standoff Height: 0mm; Propagation Delay: 6.1ns; Logic Function Desc: D Type; Number Of Outputs: 2; Nominal Supply Current: 10uA; Max Supply Voltage: 5.5V; Number Of Inputs: 1; Min Supply Voltage: 1.65V
U28 = CMP-0750213-2: INA293 High-Voltage, High Bandwidth, Unidirectional, 110-V Common-Mode, Current-Sense Amplifier, DBV0005A (SOT-23-5); Alternate Manufacturer: Texas Instruments; Alternate PartNumber: INA293A1IDBVT; SizeZ_mm: 1.45; AEC Qualified: N; CompType: IC; SizeAreaWB_mm2: 14.82; SizeArea_mm2: 8.12; SizeY_mm: 2.9; AEC Category: Q200; SizeX_mm: 2.8
U29 U30 = CMP-0860894-1: Low power, small size comparator with push-pull output, DCK0005A (SOT-SC70-5); Alternate Manufacturer: Texas Instruments; Alternate PartNumber: TLV7011DCKT; CompType: IC; SizeZ_mm: 1.1; SizeY_mm: 2; AEC Qualified: N; AEC Category: Q200; SizeX_mm: 2.1; SizeAreaWB_mm2: 9.3; SizeArea_mm2: 4.2; Rating: Catalog

## Sheet AC_L2_Baseboard_RCD_MCU.SchDoc
size 431 x 279 mm; Date: Not shown in title block; ApprovedBy: Not shown in title block; CheckedBy: Not shown in title block; Author: Not shown in title block; CompanyName: Not shown in title block; Engineer: Not shown in title block; Organization: Not shown in title block; Address1: Not shown in title block; Address2: Not shown in title block; Address3: Not shown in title block; Address4: Not shown in title block; DocumentNumber: 9; Revision: Use project parameter SCH_Rev; SheetNumber: 9; SheetTotal: 11; PageSetup: Record=PageOptions¦CenterHorizontal=True¦CenterVertical=True¦PrintScale=1.00¦XCorrection=1.00¦YCorrection=1.00¦PrintKind=0¦BorderSize=5000000¦LeftOffset=0¦BottomOffset=0¦Orientation=2¦PaperLength=1000¦PaperWidth=1000¦Scale=100¦PaperSource=15¦PrintQuality=600¦MediaType=1¦DitherType=10¦PaperKind=Letter¦PrintScaleMode=1
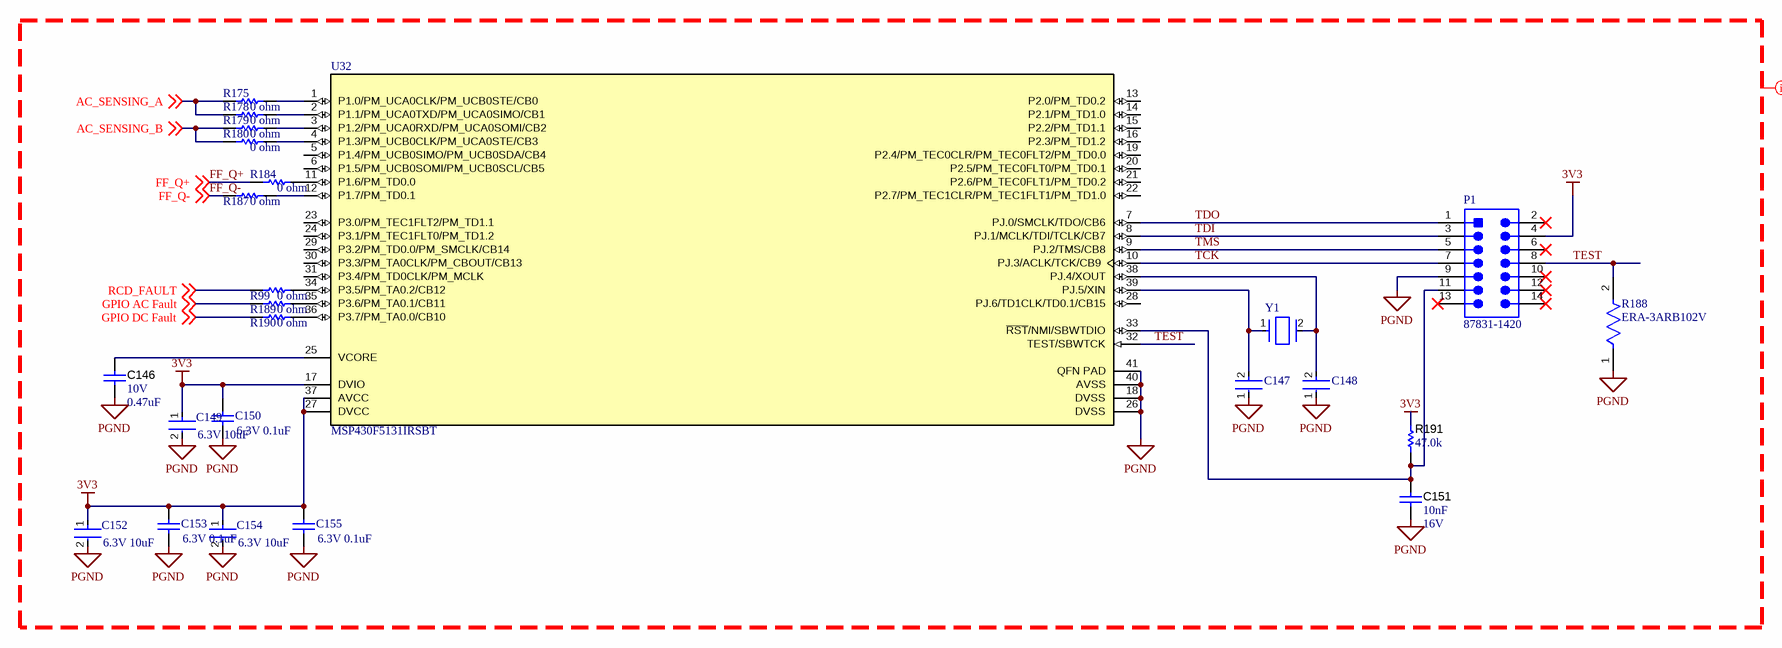
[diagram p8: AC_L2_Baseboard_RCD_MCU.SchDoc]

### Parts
C146  VDC_V: 10V  ValueDisplayed: 0.47uF  [0402]  (hidden comment: GRM155R61A474KE15D)
C147  C1608NP01H060D080AA  [FP-C1608-080-0_1-IPC_B]  (value not drawn)
C148  C1608NP01H060D080AA  [FP-C1608-080-0_1-IPC_B]  (value not drawn)
C149  6.3V 10uF  [FP-GRM155-0_2-MFG]
C150  6.3V 0.1uF  [CAPC1005X56X25NL10T15]
C151  Cap_F: 10nF  VDC_V: 16V  [0603]  (hidden comment: C0603C103K4RACTU)
C152  6.3V 10uF  [FP-GRM155-0_2-MFG]
C153  6.3V 0.1uF  [CAPC1005X56X25NL10T15]
C154  6.3V 10uF  [FP-GRM155-0_2-MFG]
C155  6.3V 0.1uF  [CAPC1005X56X25NL10T15]
P1  87831-1420  [MOLEX-87831-1420_V]
R99  0 ohm  [RESC1005X40X25NL05T10]
R175  0 ohm  [RESC1005X40X25NL05T10]
R178  0 ohm  [RESC1005X40X25NL05T10]
R179  0 ohm  [RESC1005X40X25NL05T10]
R180  0 ohm  [RESC1005X40X25NL05T10]
R184  0 ohm  [RESC1005X40X25NL05T10]
R187  0 ohm  [RESC1005X40X25NL05T10]
R188  ERA-3ARB102V  [FP-ERA3A-IPC_B]
R189  0 ohm  [RESC1005X40X25NL05T10]
R190  0 ohm  [RESC1005X40X25NL05T10]
R191  ValueDisplayed: 47.0k  [0603]  (hidden comment: RC0603FR-0747KL)
U32  MSP430F5131IRSBT  [RSB0040B]
Y1  ABS10-32.768KHZ-1-T  [FP-ABS10-MFG]  (value not drawn)

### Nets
3V3: C149.1 C150.2 C152.1 C153.2 C154.1 C155.2 P1.4 R191.2 U32.17(DVIO) U32.27(DVCC) U32.37(AVCC)
PGND: C146.2 C147.1 C148.1 C149.2 C150.1 C151.2 C152.2 C153.1 C154.2 C155.1 P1.9 R188.1 U32.18(DVSS) U32.26(DVSS) U32.40(AVSS) U32.41(QFN_PAD)
AC_SENSING_A: R175.1 R178.1 ; off-sheet AC_SENSING_A
AC_SENSING_B: R179.1 R180.1 ; off-sheet AC_SENSING_B
FF_Q+: R184.1 ; off-sheet FF_Q+
FF_Q-: R187.1 ; off-sheet FF_Q-
GPIO AC Fault: R189.1 ; off-sheet GPIO AC Fault
GPIO DC Fault: R190.1 ; off-sheet GPIO DC Fault
RCD_FAULT: R99.1 ; off-sheet RCD_FAULT
TCK: P1.7 U32.10(PJ.3/ACLK/TCK/CB9)
TDI: P1.3 U32.8(PJ.1/MCLK/TDI/TCLK/CB7)
TDO: P1.1 U32.7(PJ.0/SMCLK/TDO/CB6)
TEST: P1.8 R188.2 U32.32(TEST/SBWTCK)
TMS: P1.5 U32.9(PJ.2/TMS/CB8)
NetC146_1: C146.1 U32.25(VCORE)
NetC147_2: C147.2 U32.39(PJ.5/XIN) Y1.1
NetC148_2: C148.2 U32.38(PJ.4/XOUT) Y1.2
NetC151_1: C151.1 P1.11 R191.1 U32.33(~{RST}/NMI/SBWTDIO)
NetR99_2: R99.2 U32.34(P3.5/PM_TA0.2/CB12)
NetR175_2: R175.2 U32.1(P1.0/PM_UCA0CLK/PM_UCB0STE/CB0)
NetR178_2: R178.2 U32.2(P1.1/PM_UCA0TXD/PM_UCA0SIMO/CB1)
NetR179_2: R179.2 U32.3(P1.2/PM_UCA0RXD/PM_UCA0SOMI/CB2)
NetR180_2: R180.2 U32.4(P1.3/PM_UCB0CLK/PM_UCA0STE/CB3)
NetR184_2: R184.2 U32.11(P1.6/PM_TD0.0)
NetR187_2: R187.2 U32.12(P1.7/PM_TD0.1)
NetR189_2: R189.2 U32.35(P3.6/PM_TA0.1/CB11)
NetR190_2: R190.2 U32.36(P3.7/PM_TA0.0/CB10)

Not connected (* = marked no-connect by the designer): P1 2* 6* 10* 12* 13* 14*; U32 5(P1.4/PM_UCB0SIMO/PM_UCB0SDA/CB4) 6(P1.5/PM_UCB0SOMI/PM_UCB0SCL/CB5) 13(P2.0/PM_TD0.2) 14(P2.1/PM_TD1.0) 15(P2.2/PM_TD1.1) 16(P2.3/PM_TD1.2) 19(P2.4/PM_TEC0CLR/PM_TEC0FLT2/PM_TD0.0) 20(P2.5/PM_TEC0FLT0/PM_TD0.1) 21(P2.6/PM_TEC0FLT1/PM_TD0.2) 22(P2.7/PM_TEC1CLR/PM_TEC1FLT1/PM_TD1.0) 23(P3.0/PM_TEC1FLT2/PM_TD1.1) 24(P3.1/PM_TEC1FLT0/PM_TD1.2) 28(PJ.6/TD1CLK/TD0.1/CB15) 29(P3.2/PM_TD0.0/PM_SMCLK/CB14) 30(P3.3/PM_TA0CLK/PM_CBOUT/CB13) 31(P3.4/PM_TD0CLK/PM_MCLK)

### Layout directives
mark named MSP430: 3V3, AC_SENSING_A, AC_SENSING_B, FF_Q+, FF_Q-, GPIO AC Fault, GPIO DC Fault, PGND, RCD_FAULT, TCK, TDI, TDO, TEST, TMS

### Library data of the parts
C146 = CMP-0006580-2: CAP, CERM, 0.47 uF, 10 V, +/- 10%, X5R, 0402; Manufacturer: MuRata; TaMin_C: -55°C; Polarized: N; SizeAreaWB_mm2: 3; Value1: Unknown; U/M: EA; Value: 0.47uF; TaMax_C: 85°C; SizeZ_mm: 0.6; SizeX_mm: 1; SizeY_mm: 0.5; Cap_F: 470nF; AEC Category: Q200
C147 C148 = CMP-08246-004279-1: Multilayer Ceramic Capacitors 6pF ±0.5pF 50V NP0 SMD 0603; Dielectric: C0G
C149 C152 C154 = CMP-06035-061139-1: Chip Multilayer Ceramic Capacitors for General Purpose, 0402, 10uF, X5R, 15%, 20%, 6.3V
C150 C153 C155 = CMP-2008-02981-1: 04026C104MAT2A; Manufacturer: AVX Interconnect / Elco
C151 = CMP-0006853-4: CAP, CERM, 0.01 uF, 16 V, +/- 10%, X7R, 0603; Manufacturer: Kemet; TaMin_C: -55°C; Polarized: N; SizeAreaWB_mm2: 4.68; Value1: Unknown; U/M: EA; Value: 0.01uF; TaMax_C: 125°C; SizeZ_mm: 1; SizeX_mm: 1.6; SizeY_mm: 0.8; SizeArea_mm2: 1.28; AEC Category: Q200
P1 = CMP-2000-05240-1: Header, Pitch 2 mm, 2 x 7 Position, Height 6.4 mm, Tail Length 2.5 mm, -55 to 105 degC, RoHS, Tube; Number of Positions / Contacts: 14; Current Rating: 2A; Brand: Molex; Mounting Angle: Vertical; Pitch: 2mm; Voltage Rating: 125V
R99 R175 R178-R180 R184 R187 R189 R190 = CMP-2002-06970-1: RC0402JR-100RL; Manufacturer: Yageo
R188 = CMP-05422-000100-1: RES SMD 1K OHM 0.1% 1/10W 0603; Voltage Rating (DC): 150V; Power Rating: 100mW; Temperature Coefficient: 10ppm/°C; Voltage Rating: 75V; Resistance: 1kR
R191 = CMP-0023133-5: RES, 47.0 k, 1%, 0.1 W, 0603; Manufacturer: Yageo; Power_W: 100mW; TempCo: 100 ppm/C; Value_Code: 47k0; Value: 47.0k; Res_ohm: 47k; SizeX_mm: 1.6; SizeY_mm: 0.8; SizeZ_mm: 1; Value2: 0.1W; SizeArea_mm2: 1.28; AEC Qualified: N; VDC_V: 75V; AEC Category: Q200; SizeAreaWB_mm2: 4.68
U32 = CMP-0038830-4: MSP430F51x2 Mixed Signal Microcontroller, RSB0040B (WQFN-40); Manufacturer: Texas Instruments; SRAM(B): 1024; AEC Qualified: N; GPIO: 29; USCI_A (UART/LIN/IrDA/SPI): 1; Frequency(MHz): 25; Timers - 16-bit: 3; SVS: Yes; SizeArea_mm2: 25.0; SizeZ_mm: 0.8; Rating: Catalog; SizeAreaWB_mm2: 49.0; CompType: IC; Flash(KB): 8; AEC Category: Q200; Multiplier: 32x32; SizeY_mm: 5.0
Y1 = CMP-27762-013278-1: CRYSTAL 32.7680KHZ 12.5PF SMD; Frequency Tolerance: 10ppm; ESR (Equivalent Series Resistance): 70kR

## Sheet AC_L2_Baseboard_Connectors.SchDoc
size 431 x 279 mm; DocumentNumber: 10; SheetNumber: 10; SheetTotal: 11; PageSetup: Record=PageOptions¦CenterHorizontal=True¦CenterVertical=True¦PrintScale=0.69¦XCorrection=1.00¦YCorrection=1.00¦PrintKind=0¦BorderSize=5000000¦LeftOffset=0¦BottomOffset=0¦Orientation=2¦PaperLength=1000¦PaperWidth=1000¦Scale=100¦PaperSource=15¦PrintQuality=600¦MediaType=1¦DitherType=10¦PaperKind=Letter¦PrintScaleMode=1
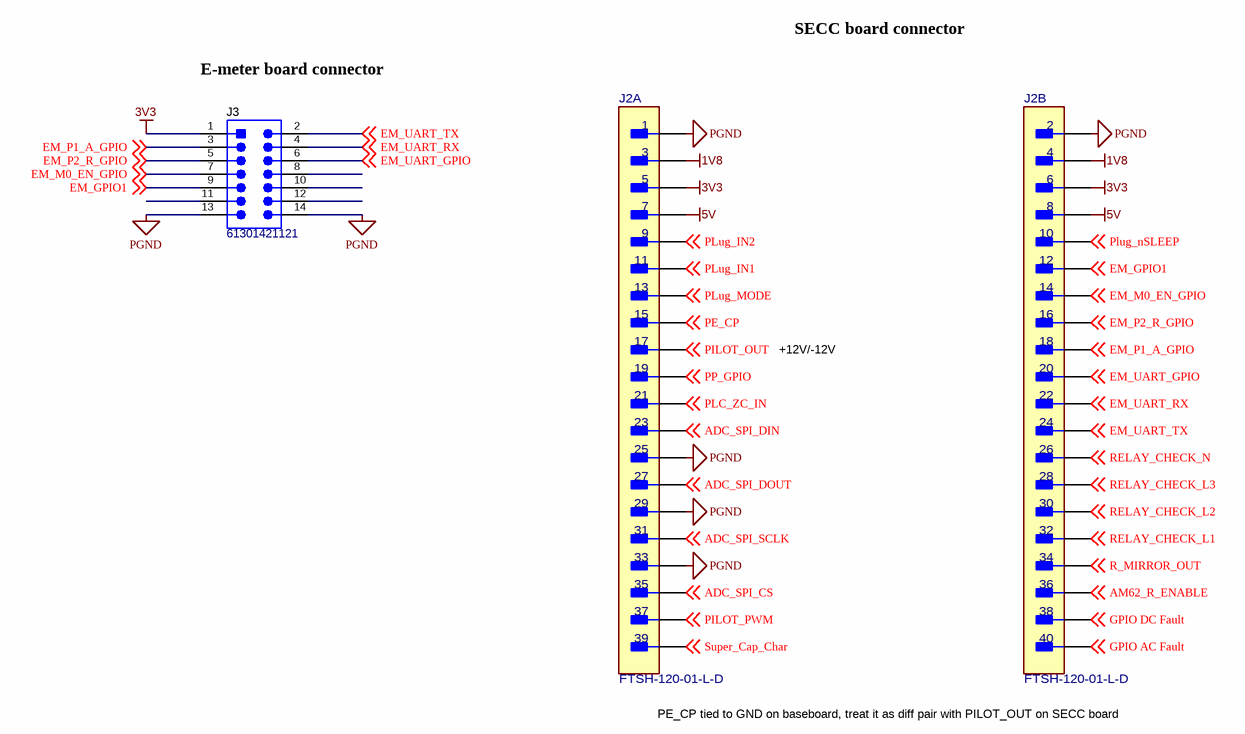
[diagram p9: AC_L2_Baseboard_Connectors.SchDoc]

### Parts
J2  FTSH-120-01-L-D  [FP-FTSH-120-01-L-D_HDR40-MFG]  (parts A,B of 2)
J3  61301421121  [Wurth_61301421121]

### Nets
1V8: J2.3 J2.4
3V3: J2.5 J2.6 J3.1
5V: J2.7 J2.8
PGND: J2.1 J2.2 J2.25 J2.29 J2.33 J3.13 J3.14
ADC_SPI_CS: J2.35 ; off-sheet ADC_SPI_CS
ADC_SPI_DIN: J2.23 ; off-sheet ADC_SPI_DIN
ADC_SPI_DOUT: J2.27 ; off-sheet ADC_SPI_DOUT
ADC_SPI_SCLK: J2.31 ; off-sheet ADC_SPI_SCLK
AM62_R_ENABLE: J2.36 ; off-sheet AM62_R_ENABLE
EM_GPIO1: J2.12 J3.9 ; off-sheet EM_GPIO1
EM_M0_EN_GPIO: J2.14 J3.7 ; off-sheet EM_M0_EN_GPIO
EM_P1_A_GPIO: J2.18 J3.3 ; off-sheet EM_P1_A_GPIO
EM_P2_R_GPIO: J2.16 J3.5 ; off-sheet EM_P2_R_GPIO
EM_UART_GPIO: J2.20 J3.6 ; off-sheet EM_UART_GPIO
EM_UART_RX: J2.22 J3.4 ; off-sheet EM_UART_RX
EM_UART_TX: J2.24 J3.2 ; off-sheet EM_UART_TX
GPIO AC Fault: J2.40 ; off-sheet GPIO AC Fault
GPIO DC Fault: J2.38 ; off-sheet GPIO DC Fault
PE_CP: J2.15 ; off-sheet PE_CP
PILOT_OUT: J2.17 ; off-sheet PILOT_OUT
PILOT_PWM: J2.37 ; off-sheet PILOT_PWM
PLC_ZC_IN: J2.21 ; off-sheet PLC_ZC_IN
PLug_IN1: J2.11 ; off-sheet PLug_IN1
PLug_IN2: J2.9 ; off-sheet PLug_IN2
PLug_MODE: J2.13 ; off-sheet PLug_MODE
Plug_nSLEEP: J2.10 ; off-sheet Plug_nSLEEP
PP_GPIO: J2.19 ; off-sheet PP_GPIO
R_MIRROR_OUT: J2.34 ; off-sheet R_MIRROR_OUT
RELAY_CHECK_L1: J2.32 ; off-sheet RELAY_CHECK_L1
RELAY_CHECK_L2: J2.30 ; off-sheet RELAY_CHECK_L2
RELAY_CHECK_L3: J2.28 ; off-sheet RELAY_CHECK_L3
RELAY_CHECK_N: J2.26 ; off-sheet RELAY_CHECK_N
Super_Cap_Char: J2.39 ; off-sheet Super_Cap_Char

Not connected (* = marked no-connect by the designer): J3 8 10 11 12

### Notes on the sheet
- SECC board connector
- E-meter board connector
- +12V/-12V
- PE_CP tied to GND on baseboard, treat it as diff pair with PILOT_OUT on SECC board

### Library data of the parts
J2 = CMP-0095404-1: Manufacturer: Samtec; Row_Count: 2; Conn Orientation: Vertical; Conn Gender: Male; Current_A: 3.4A; SizeZ_mm: 5.82mm; AEC Qualified: No; DUT-Pitch_mm: 1.27mm; ContactFinish: Gold,Nickel
J3 = CMP-0086014-1: Header, 2.54mm, 7x2, Gold, TH; Manufacturer: Wurth Elektronik; Pitch_mm: 2.54; Voltage_V: 250V; Shrouded: N; Gender: Male; Current_A: 3A; Cert_UL: Y; Row_Count: 2

## Sheet AC_L2_Baseboard_Hardware.SchDoc
size 431 x 279 mm; Date: Not shown in title block; ApprovedBy: Not shown in title block; CheckedBy: Not shown in title block; Author: Not shown in title block; CompanyName: Not shown in title block; Engineer: Not shown in title block; Organization: Not shown in title block; Address1: Not shown in title block; Address2: Not shown in title block; Address3: Not shown in title block; Address4: Not shown in title block; DocumentNumber: 11; Revision: Use project parameter SCH_Rev; SheetNumber: 11; SheetTotal: 11; PageSetup: Record=PageOptions¦CenterHorizontal=True¦CenterVertical=True¦PrintScale=1.00¦XCorrection=1.00¦YCorrection=1.00¦PrintKind=0¦BorderSize=5000000¦LeftOffset=0¦BottomOffset=0¦Orientation=2¦PaperLength=1000¦PaperWidth=1000¦Scale=100¦PaperSource=15¦PrintQuality=600¦MediaType=1¦DitherType=10¦PaperKind=Letter¦PrintScaleMode=1
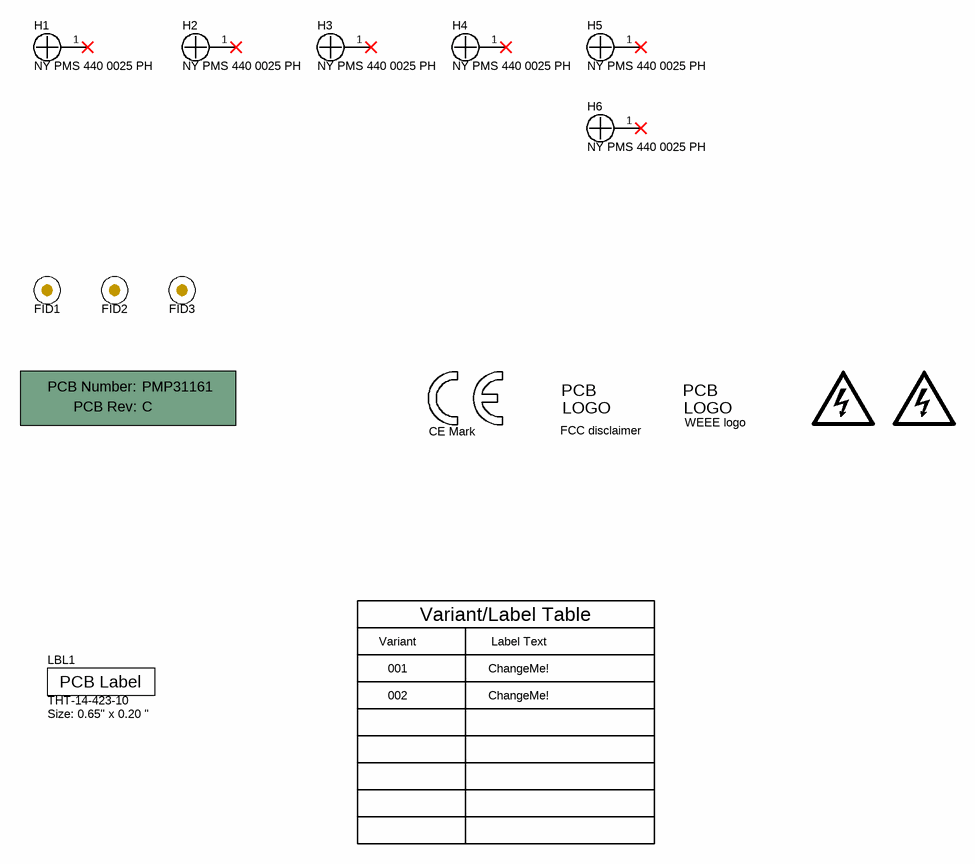
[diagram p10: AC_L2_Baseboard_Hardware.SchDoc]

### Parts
!PCB  Printed Circuit Board  (value not drawn)  (mechanical)
FID1  Fiducial  [Fiducial10-20]  (value not drawn)
FID2  Fiducial  [Fiducial10-20]  (value not drawn)
FID3  Fiducial  [Fiducial10-20]  (value not drawn)
H1  NY PMS 440 0025 PH  [NY PMS 440 0025 PH]
H2  NY PMS 440 0025 PH  [NY PMS 440 0025 PH]
H3  NY PMS 440 0025 PH  [NY PMS 440 0025 PH]
H4  NY PMS 440 0025 PH  [NY PMS 440 0025 PH]
H5  NY PMS 440 0025 PH  [NY PMS 440 0025 PH]
H6  NY PMS 440 0025 PH  [NY PMS 440 0025 PH]
LBL1  THT-14-423-10  Note: Size: 0.65" x 0.20 "  [Label_650x200]
LOGO1  DANGER HIGH VOLTAGE  [IEC_HighVoltage_Medium]  (value not drawn)  (no BOM)
Logo2  CE Mark  [CE_Mark_5mm]  (no BOM)
Logo3  FCC disclaimer  [FCC_disclaimer]  (no BOM)
Logo4  WEEE logo  [WEEE_Minimum]  (no BOM)
LOGO5  DANGER HIGH VOLTAGE  [IEC_HighVoltage_Medium]  (value not drawn)  (no BOM)

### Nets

Not connected (* = marked no-connect by the designer): H1 1*; H2 1*; H3 1*; H4 1*; H5 1*; H6 1*

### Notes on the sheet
- Variant
- Variant/Label Table
- Label Text
- 001
- 002
- ChangeMe!

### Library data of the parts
!PCB = CMP-0003618-2: Manufacturer: Any; PartNumber: PMP31161
FID1-FID3 = CMP-0077181-1: Fiducial mark.  There is nothing to buy or mount.
H1-H6 = CMP-0003617-1: Machine Screw, Round, #4-40 x 1/4, Nylon, Philips panhead; Manufacturer: B&F Fastener Supply; CompType: Hardware
LBL1 = CMP-0003625-1: Thermal Transfer Printable Labels, 0.650" W x 0.200" H - 10,000 per roll; Manufacturer: Brady; CompType: Label
LOGO1 LOGO5 = CMP-0074835-1: IEC 61010-1 High Voltage Warning; SymbolCreator: a0412235; Lib Reference: IEC_HighVoltage
Logo2 = CMP-0074844-1: SymbolCreator: a0412235
Logo3 = CMP-0074847-1: FCC_disclaimer; Library Reference: Logo
Logo4 = CMP-0074769-1

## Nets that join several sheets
1V8: AC_L2_Baseboard SCH-POL_PWR (C78_P.1 TP16_P.1 U11_P.5), AC_L2_Baseboard_Connectors (J2.3 J2.4)
3V3: AC_L2_Baseboard SCH-POL_PWR (6 pins), AC_L2_Baseboard_Relay_Weld_Detect (15 pins), AC_L2_Baseboard_HPGP_ZC (R82.2), AC_L2_Baseboard_Pilot_Wire_ADC (5 pins), AC_L2_Baseboard_PlugLock (R126.1), AC_L2_Baseboard_RCD (16 pins), AC_L2_Baseboard_RCD_MCU (11 pins), AC_L2_Baseboard_Connectors (J2.5 J2.6 J3.1)
5V: AC_L2_Baseboard SCH-POL_PWR (7 pins), AC_L2_Baseboard_Connectors (J2.7 J2.8)
12V_In: AC_L2_Baseboard SCH-Flyback_PWR (13 pins), AC_L2_Baseboard_Relay_Weld_Detect (F5.2), AC_L2_Baseboard_PlugLock (F4.2), AC_L2_Baseboard_RCD (C138.1 C139.1 C140.1 U26.1)
+12Va: AC_L2_Baseboard SCH-POL_PWR (7 pins), AC_L2_Baseboard_Pilot_Wire_ADC (C99.1 U18.6), AC_L2_Baseboard_RCD (9 pins)
-12Va: AC_L2_Baseboard SCH-POL_PWR (7 pins), AC_L2_Baseboard_Pilot_Wire_ADC (C100.1 U18.2 U18.5), AC_L2_Baseboard_RCD (8 pins)
PGND: AC_L2_Baseboard SCH-Flyback_PWR (33 pins), AC_L2_Baseboard SCH-POL_PWR (63 pins), AC_L2_Baseboard_Relay_Weld_Detect (22 pins), AC_L2_Baseboard_HPGP_ZC (C96.2 C98.1 U14.3), AC_L2_Baseboard_Pilot_Wire_ADC (10 pins), AC_L2_Baseboard_PlugLock (5 pins), AC_L2_Baseboard_RCD (31 pins), AC_L2_Baseboard_RCD_MCU (16 pins), AC_L2_Baseboard_Connectors (7 pins)
+12V: AC_L2_Baseboard SCH-Flyback_PWR (5 pins), AC_L2_Baseboard SCH-POL_PWR (5 pins)
+14V: AC_L2_Baseboard SCH-Flyback_PWR (D1_P.1 D3_P.1), AC_L2_Baseboard SCH-POL_PWR (C44_P.1 D21_P.1 U8_P.1 U8_P.2)
+14V_INV: AC_L2_Baseboard SCH-Flyback_PWR (D1_P.2), AC_L2_Baseboard SCH-POL_PWR (5 pins)
+14V_SW: AC_L2_Baseboard SCH-Flyback_PWR (D2_P.2 D15_P.2 R1_P.1 T1_P.14), AC_L2_Baseboard SCH-POL_PWR (D23_P.2)
-14V: AC_L2_Baseboard SCH-Flyback_PWR (D5_P.2 D8_P.2), AC_L2_Baseboard SCH-POL_PWR (C53_P.1 D24_P.2 U8_P.5)
-14V_INV: AC_L2_Baseboard SCH-Flyback_PWR (D5_P.1), AC_L2_Baseboard SCH-POL_PWR (5 pins)
AC_SENSING_A: AC_L2_Baseboard_RCD (C130.2 R135.2 R144.1 U24.1), AC_L2_Baseboard_RCD_MCU (R175.1 R178.1)
AC_SENSING_B: AC_L2_Baseboard_RCD (R138.2 U22.1), AC_L2_Baseboard_RCD_MCU (R179.1 R180.1)
ADC_SPI_CS: AC_L2_Baseboard_Pilot_Wire_ADC (U19.1), AC_L2_Baseboard_Connectors (J2.35)
ADC_SPI_DIN: AC_L2_Baseboard_Pilot_Wire_ADC (U19.6), AC_L2_Baseboard_Connectors (J2.23)
ADC_SPI_DOUT: AC_L2_Baseboard_Pilot_Wire_ADC (U19.7), AC_L2_Baseboard_Connectors (J2.27)
ADC_SPI_SCLK: AC_L2_Baseboard_Pilot_Wire_ADC (U19.8), AC_L2_Baseboard_Connectors (J2.31)
AM62_R_ENABLE: AC_L2_Baseboard_Relay_Weld_Detect (U36.2), AC_L2_Baseboard_Connectors (J2.36)
FF_Q+: AC_L2_Baseboard_RCD (U26.6 U27.5), AC_L2_Baseboard_RCD_MCU (R184.1)
FF_Q-: AC_L2_Baseboard_RCD (R154.1 U27.3), AC_L2_Baseboard_RCD_MCU (R187.1)
Fly_ON: AC_L2_Baseboard SCH-Flyback_PWR (Q5_P.1), AC_L2_Baseboard SCH-POL_PWR (5 pins)
GPIO AC Fault: AC_L2_Baseboard_RCD_MCU (R189.1), AC_L2_Baseboard_Connectors (J2.40)
GPIO DC Fault: AC_L2_Baseboard_RCD_MCU (R190.1), AC_L2_Baseboard_Connectors (J2.38)
LINE1_IN: AC_L2_Baseboard SCH-Flyback_PWR (F1_P.2 TP1_P.1), AC_L2_Baseboard_Relay_Weld_Detect (J19.1 K1.1 R204.2), AC_L2_Baseboard_HPGP_ZC (C95.1)
LINE2_IN: AC_L2_Baseboard SCH-Flyback_PWR (F2_P.2 TP2_P.1), AC_L2_Baseboard_Relay_Weld_Detect (J21.1 K1.2)
LINE3_IN: AC_L2_Baseboard SCH-Flyback_PWR (F3_P.2 TP3_P.1), AC_L2_Baseboard_Relay_Weld_Detect (J23.1 K1.3)
N_IN: AC_L2_Baseboard SCH-Flyback_PWR (8 pins), AC_L2_Baseboard_Relay_Weld_Detect (8 pins), AC_L2_Baseboard_HPGP_ZC (D34.2 U14.2)
PE_CP: AC_L2_Baseboard_Pilot_Wire_ADC (6 pins), AC_L2_Baseboard_Connectors (J2.15)
PILOT_OUT: AC_L2_Baseboard_Pilot_Wire_ADC (5 pins), AC_L2_Baseboard_Connectors (J2.17)
PILOT_PWM: AC_L2_Baseboard_Pilot_Wire_ADC (TP25.1 U18.4), AC_L2_Baseboard_Connectors (J2.37)
PLC_ZC_IN: AC_L2_Baseboard_HPGP_ZC (C97.2), AC_L2_Baseboard_Connectors (J2.21)
PLug_IN1: AC_L2_Baseboard_PlugLock (U20.6), AC_L2_Baseboard_Connectors (J2.11)
PLug_IN2: AC_L2_Baseboard_PlugLock (U20.5), AC_L2_Baseboard_Connectors (J2.9)
PLug_MODE: AC_L2_Baseboard_PlugLock (R125.2), AC_L2_Baseboard_Connectors (J2.13)
Plug_nSLEEP: AC_L2_Baseboard_PlugLock (R126.2 U20.8), AC_L2_Baseboard_Connectors (J2.10)
PP_GPIO: AC_L2_Baseboard_Pilot_Wire_ADC (Q9.1), AC_L2_Baseboard_Connectors (J2.19)
R_MIRROR_OUT: AC_L2_Baseboard_Relay_Weld_Detect (K1.7 R218.1 TP28.1), AC_L2_Baseboard_Connectors (J2.34)
RCD_FAULT: AC_L2_Baseboard_Relay_Weld_Detect (R210.1 U36.1), AC_L2_Baseboard_RCD_MCU (R99.1)
RELAY_CHECK_L1: AC_L2_Baseboard_Relay_Weld_Detect (R219.1 U33.4), AC_L2_Baseboard_Connectors (J2.32)
RELAY_CHECK_L2: AC_L2_Baseboard_Relay_Weld_Detect (R220.1 U33.5), AC_L2_Baseboard_Connectors (J2.30)
RELAY_CHECK_L3: AC_L2_Baseboard_Relay_Weld_Detect (R221.1 U34.4), AC_L2_Baseboard_Connectors (J2.28)
RELAY_CHECK_N: AC_L2_Baseboard_Relay_Weld_Detect (R222.1 U34.5), AC_L2_Baseboard_Connectors (J2.26)
Super_Cap_Char: AC_L2_Baseboard SCH-Flyback_PWR (TP10_P.1 U5_P.5), AC_L2_Baseboard_Connectors (J2.39)
Vbackup: AC_L2_Baseboard SCH-Flyback_PWR (6 pins), AC_L2_Baseboard SCH-POL_PWR (5 pins)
